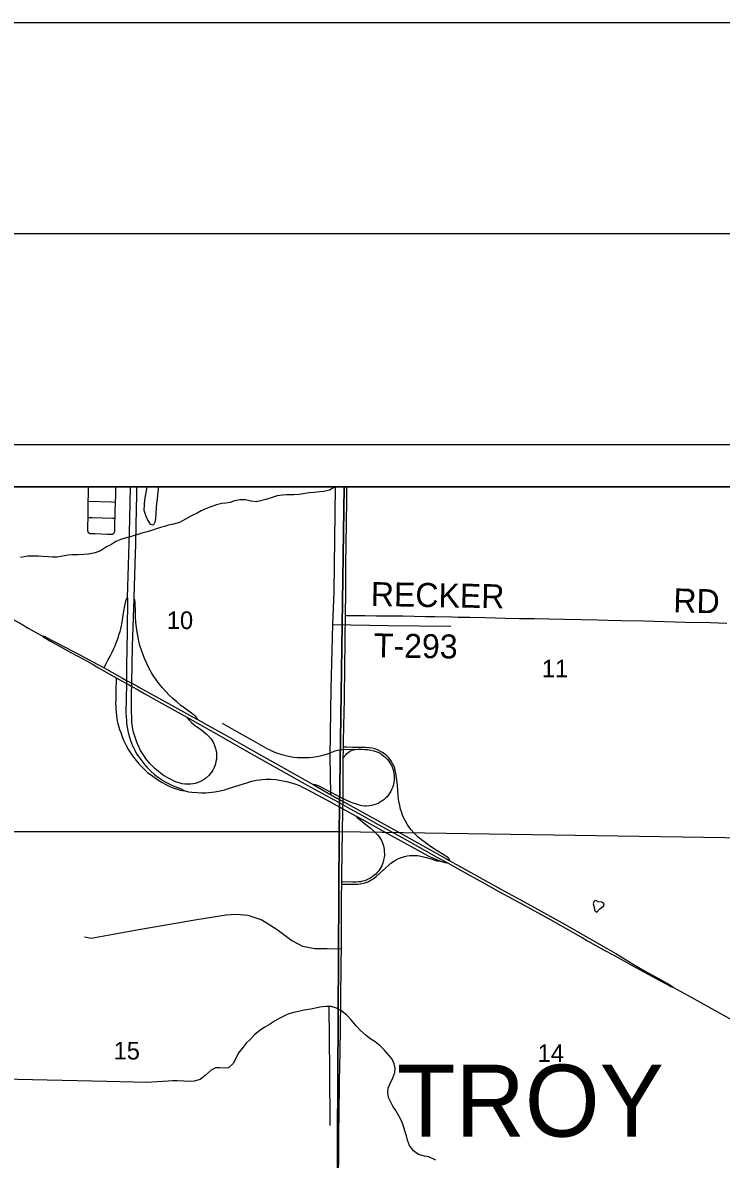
# Model space of a CAD drawing. Extents: x 0 to 34, y 0 to 22.
# Drawn here: x 4.765 to 6.42, y 19.306 to 22 of the extents above; entities that cross this region are included whole.
import ezdxf

# ---------------------------------------------------------------- set-up
doc = ezdxf.new("R2010")
doc.units = 0
for name, color, linetype in [('GM_X_City_Street', 7, 'Continuous'), ('GM_X_County_Road', 7, 'Continuous'), ('GM_X_Interchange_Ramps', 7, 'Continuous'), ('GM_X_Minor_Lake', 7, 'Continuous'), ('GM_X_Minor_River', 7, 'Continuous'), ('GM_X_Section', 7, 'Continuous'), ('GM_X_Section_Text', 7, 'Continuous'), ('GM_X_State_Route', 7, 'Continuous'), ('GM_X_Township_Road', 7, 'Continuous'), ('GM_X_Township_Road_Text', 7, 'Continuous'), ('GM_X_Township_Text', 7, 'Continuous'), ('GM_X_US_Route', 7, 'Continuous'), ('SH_Border', 7, 'Continuous'), ('SH_Cut_Line', 7, 'Continuous'), ('SH_Data', 7, 'Continuous')]:
    doc.layers.add(name, color=color, linetype=linetype)

msp = doc.modelspace()

# ---------------------------------------------------------------- linework, layer by layer
at = {"layer": 'GM_X_City_Street'}
for points in [[(5.527, 20.9), (4.528, 20.9), (4.5187, 20.0828), (5.5144, 20.0832)], [(6.5392, 20.9), (5.527, 20.9), (5.5144, 20.0832), (6.5307, 20.0674)]]:
    msp.add_lwpolyline(points, close=True, dxfattribs=at)
at = {"layer": 'GM_X_County_Road'}
for p, q in [((5.5246, 20.2575), (5.525, 20.2775)), ((5.525, 20.2775), (5.5251, 20.283)), ((5.5209, 19.9584), (5.521, 19.9635))]:
    msp.add_line(p, q, dxfattribs=at)
for points in [[(5.53, 20.5953), (5.5301, 20.6052), (5.5309, 20.6408), (5.5307, 20.6432), (5.5306, 20.6463), (5.5306, 20.6699), (5.5307, 20.681), (5.5308, 20.7165), (5.532, 20.8122), (5.5328, 20.8707), (5.533, 20.9)], [(5.5282, 20.4449), (5.5286, 20.4642), (5.5294, 20.5406), (5.53, 20.5953)], [(5.5251, 20.283), (5.5252, 20.3001), (5.5258, 20.3287), (5.5266, 20.3697), (5.5271, 20.392), (5.5278, 20.4287), (5.5282, 20.4449)], [(5.5238, 20.1423), (5.5239, 20.1461), (5.5241, 20.1541), (5.5241, 20.1556), (5.5242, 20.1605), (5.5243, 20.1661), (5.5244, 20.1909), (5.5245, 20.2504), (5.5246, 20.2575)], [(5.521, 19.9635), (5.5212, 19.9805), (5.522, 20.0334), (5.523, 20.0857), (5.5235, 20.1286), (5.5237, 20.1365), (5.5238, 20.1423)], [(5.5127, 19.2322), (5.5137, 19.3106), (5.5139, 19.3298), (5.5141, 19.3564), (5.5151, 19.4267), (5.5151, 19.4385), (5.5155, 19.4614), (5.5159, 19.4869), (5.5167, 19.5286), (5.517, 19.5572), (5.5177, 19.62), (5.5185, 19.6784), (5.5195, 19.7723), (5.52, 19.8022), (5.52, 19.8158), (5.5203, 19.8643), (5.5201, 19.8942), (5.5204, 19.9271), (5.5209, 19.9584)]]:
    msp.add_lwpolyline(points, dxfattribs=at)
at = {"layer": 'GM_X_Interchange_Ramps'}
for points in [[(5.0127, 20.6371), (5.0125, 20.557), (5.0109, 20.4754), (5.0106, 20.441), (5.0104, 20.434), (5.0098, 20.3976), (5.0095, 20.3658), (5.0096, 20.3549), (5.0104, 20.3453), (5.011, 20.3391), (5.0123, 20.3299), (5.0142, 20.3213), (5.0158, 20.3141), (5.0179, 20.3068), (5.0204, 20.2988), (5.0226, 20.2924), (5.0253, 20.2861), (5.028, 20.2804), (5.0311, 20.2742), (5.0348, 20.2672), (5.0397, 20.2598), (5.0467, 20.25), (5.054, 20.2407), (5.059, 20.2351), (5.0678, 20.2264), (5.0781, 20.2175), (5.0864, 20.211), (5.0938, 20.2058), (5.1007, 20.2016), (5.109, 20.1971), (5.1197, 20.192), (5.1289, 20.1883), (5.1385, 20.1848), (5.1444, 20.182), (5.1493, 20.1791)], [(5.1809, 20.3472), (5.1795, 20.349), (5.178, 20.351), (5.1761, 20.3536), (5.1747, 20.3552), (5.1729, 20.357), (5.1646, 20.3631), (5.1502, 20.3738), (5.1398, 20.3818), (5.1297, 20.39), (5.1203, 20.3982), (5.1118, 20.4064), (5.1036, 20.4149), (5.0958, 20.4238), (5.0883, 20.4329), (5.082, 20.4414), (5.0756, 20.4506), (5.0694, 20.4607), (5.0637, 20.471), (5.0588, 20.4811), (5.0543, 20.4913), (5.0501, 20.5017), (5.0461, 20.5128), (5.0427, 20.5241), (5.0401, 20.5337), (5.038, 20.5434), (5.0359, 20.5551), (5.0343, 20.5662), (5.0331, 20.5779), (5.0323, 20.5928), (5.0319, 20.6095), (5.0315, 20.6189), (5.0311, 20.6282), (5.0305, 20.6312), (5.029, 20.635)], [(4.9865, 20.4469), (4.9856, 20.4121), (4.9852, 20.3968), (4.9849, 20.3867), (4.9851, 20.3802), (4.9855, 20.3734), (4.986, 20.3667), (4.987, 20.3559), (4.9887, 20.3455), (4.9902, 20.3389), (4.9919, 20.3332), (4.9944, 20.3247), (4.9969, 20.3176), (4.9997, 20.3094), (5.0037, 20.2992), (5.0097, 20.2864), (5.0156, 20.2764), (5.0204, 20.2691), (5.0248, 20.2624), (5.0304, 20.2549), (5.0399, 20.2434), (5.0508, 20.232), (5.0606, 20.2231), (5.0728, 20.2138), (5.0851, 20.2053), (5.0955, 20.1991), (5.1038, 20.1945), (5.1154, 20.1889), (5.1233, 20.1856), (5.1314, 20.183), (5.1381, 20.181), (5.1437, 20.18), (5.1493, 20.1791)], [(5.525, 20.2775), (5.5512, 20.2777), (5.5525, 20.2772), (5.5534, 20.2774), (5.5596, 20.2778), (5.5677, 20.2777), (5.5758, 20.2774), (5.5833, 20.2769), (5.59, 20.276), (5.5967, 20.2744), (5.602, 20.2727), (5.6066, 20.2707), (5.6116, 20.2682), (5.6163, 20.2652), (5.6207, 20.2618), (5.6249, 20.2581), (5.6288, 20.2541), (5.6324, 20.2497), (5.6352, 20.2457), (5.638, 20.2408), (5.6402, 20.2363), (5.6421, 20.2311), (5.6435, 20.2263), (5.6446, 20.2208), (5.6453, 20.2153), (5.6455, 20.2103), (5.6453, 20.2047), (5.6447, 20.1998), (5.6436, 20.1943), (5.642, 20.1889), (5.64, 20.1837), (5.6376, 20.1786), (5.6351, 20.1743), (5.6319, 20.1697), (5.6284, 20.1654), (5.6249, 20.1618), (5.6207, 20.1581), (5.6167, 20.1552), (5.612, 20.1522), (5.607, 20.1496), (5.6024, 20.1477), (5.5971, 20.1459), (5.5917, 20.1446), (5.5861, 20.1437), (5.5799, 20.1432), (5.5756, 20.1433), (5.5688, 20.1439), (5.5657, 20.1445), (5.5579, 20.1465), (5.5453, 20.151), (5.5366, 20.1547), (5.5242, 20.1605), (5.4687, 20.1897), (5.4632, 20.1921), (5.4589, 20.1932), (5.4533, 20.1939)], [(5.5246, 20.2575), (5.5308, 20.2646), (5.5333, 20.2674), (5.536, 20.2699), (5.539, 20.2722), (5.5422, 20.2741), (5.5462, 20.2758), (5.5504, 20.2769), (5.5525, 20.2772)], [(5.7772, 20.0136), (5.7762, 20.0159), (5.7754, 20.018), (5.7741, 20.02), (5.7721, 20.0218), (5.7703, 20.023), (5.755, 20.0321), (5.7408, 20.0411), (5.7279, 20.0498), (5.7183, 20.0567), (5.7098, 20.063), (5.7022, 20.0694), (5.6958, 20.0754), (5.6915, 20.0798), (5.6854, 20.0869), (5.6805, 20.0934), (5.676, 20.1001), (5.6719, 20.107), (5.6683, 20.1142), (5.665, 20.1217), (5.6623, 20.1293), (5.6603, 20.1358), (5.6582, 20.1443), (5.6564, 20.1547), (5.6549, 20.1676), (5.6528, 20.1924), (5.6509, 20.2098), (5.6492, 20.2215), (5.6479, 20.2275), (5.6464, 20.2329), (5.6437, 20.2399), (5.6414, 20.2443), (5.6386, 20.2491), (5.6353, 20.2537), (5.6317, 20.258), (5.6278, 20.262), (5.6236, 20.2657), (5.6191, 20.269), (5.6144, 20.272), (5.6089, 20.275), (5.6038, 20.2771), (5.599, 20.2787), (5.593, 20.2802), (5.5856, 20.2814), (5.5763, 20.2819), (5.5465, 20.2823), (5.5328, 20.2828), (5.5251, 20.283)], [(5.1493, 20.1791), (5.1577, 20.1772), (5.1659, 20.1762), (5.1782, 20.175), (5.1878, 20.1746), (5.1989, 20.1748), (5.2061, 20.1753), (5.2203, 20.177), (5.2331, 20.1793), (5.2433, 20.182), (5.2617, 20.1876), (5.2752, 20.1919), (5.2877, 20.1962), (5.298, 20.1993), (5.3081, 20.202), (5.3183, 20.2042), (5.327, 20.2055), (5.3334, 20.2061), (5.3418, 20.2066), (5.3529, 20.2066), (5.3648, 20.2058), (5.3774, 20.2039), (5.3899, 20.2015), (5.3983, 20.1994), (5.4045, 20.1975), (5.4122, 20.1949), (5.4207, 20.1916), (5.4282, 20.1882), (5.439, 20.1827), (5.4951, 20.152), (5.5237, 20.1365), (5.5548, 20.1195)], [(5.5548, 20.1195), (5.5577, 20.116), (5.5605, 20.1134), (5.5642, 20.1103), (5.5752, 20.1019), (5.5879, 20.0916), (5.5959, 20.0845), (5.6014, 20.0792), (5.6054, 20.0751), (5.6095, 20.0699), (5.6124, 20.0656), (5.615, 20.0612), (5.6165, 20.0576), (5.618, 20.0536), (5.6195, 20.0488), (5.6205, 20.0446), (5.6212, 20.0399), (5.6217, 20.034), (5.622, 20.0307), (5.622, 20.0263), (5.6216, 20.022), (5.621, 20.0185), (5.6201, 20.0144), (5.6191, 20.0108), (5.6177, 20.0066), (5.6157, 20.0016), (5.6135, 19.9975), (5.6111, 19.9934), (5.6095, 19.991), (5.607, 19.9877), (5.6042, 19.9848), (5.6016, 19.9821), (5.5964, 19.9776), (5.5926, 19.9748), (5.5876, 19.9716), (5.5836, 19.9695), (5.5789, 19.9675), (5.5753, 19.9662), (5.5709, 19.965), (5.568, 19.9644), (5.5652, 19.9639), (5.5608, 19.9634), (5.5539, 19.9631), (5.5474, 19.9631), (5.5228, 19.9635), (5.521, 19.9635)], [(5.5548, 20.1195), (5.5611, 20.1161), (5.6367, 20.0742), (5.7261, 20.0253), (5.7393, 20.019), (5.7498, 20.0146), (5.7528, 20.0135), (5.757, 20.0119), (5.7659, 20.0091), (5.7729, 20.0074)], [(5.5209, 19.9584), (5.5225, 19.9584), (5.5326, 19.9582), (5.5388, 19.9582), (5.5546, 19.9581), (5.5593, 19.9583), (5.5647, 19.9588), (5.5687, 19.9594), (5.5727, 19.9603), (5.5766, 19.9615), (5.5808, 19.9629), (5.584, 19.9643), (5.5884, 19.9664), (5.593, 19.9692), (5.5981, 19.9726), (5.6028, 19.9765), (5.6254, 19.9969), (5.6326, 20.0034), (5.6376, 20.0078), (5.6435, 20.012), (5.6481, 20.015), (5.6537, 20.0179), (5.6604, 20.0206), (5.6695, 20.0234), (5.6758, 20.0248), (5.6825, 20.0257), (5.6877, 20.0261), (5.6938, 20.0262), (5.7011, 20.0257), (5.7081, 20.0245), (5.7145, 20.0231), (5.7208, 20.0214), (5.7325, 20.0177), (5.7419, 20.0148), (5.7463, 20.0137), (5.7498, 20.0132), (5.7528, 20.0135)]]:
    msp.add_lwpolyline(points, dxfattribs=at)
at = {"layer": 'GM_X_Minor_Lake'}
msp.add_line((6.1321, 19.8986), (6.1357, 19.9021), dxfattribs=at)
for points in [[(5.0588, 20.9), (5.0579, 20.8952), (5.0531, 20.8688), (5.0521, 20.8449), (5.0567, 20.8304), (5.0614, 20.8204), (5.0672, 20.8115), (5.0728, 20.8095), (5.0759, 20.8109), (5.0791, 20.8184), (5.0807, 20.8351), (5.0822, 20.8521), (5.0839, 20.8726), (5.0863, 20.8949), (5.0864, 20.9)], [(6.1357, 19.9021), (6.1414, 19.9062), (6.1431, 19.9114), (6.1375, 19.915), (6.1288, 19.9163), (6.1228, 19.9191), (6.1194, 19.9181), (6.1166, 19.9113), (6.119, 19.9029), (6.1211, 19.8949), (6.1259, 19.8914), (6.1321, 19.8986)]]:
    msp.add_lwpolyline(points, dxfattribs=at)
at = {"layer": 'GM_X_Minor_River'}
for points in [[(5.5053, 20.9), (5.5053, 20.9), (5.4918, 20.8923), (5.4781, 20.8892), (5.4686, 20.888), (5.4553, 20.8868), (5.444, 20.8855), (5.4341, 20.8839), (5.42, 20.8819), (5.4075, 20.8807), (5.3908, 20.8807), (5.3806, 20.8802), (5.368, 20.8782), (5.3558, 20.8744), (5.3409, 20.8702), (5.3314, 20.8674), (5.3188, 20.8646), (5.3052, 20.8661), (5.2928, 20.8691), (5.2792, 20.8694), (5.267, 20.8663), (5.2567, 20.8631), (5.2464, 20.8615), (5.2369, 20.8602), (5.2244, 20.8574), (5.2106, 20.8528), (5.2003, 20.8489), (5.188, 20.8428), (5.178, 20.8373), (5.1631, 20.8301), (5.1504, 20.8236), (5.1362, 20.8155), (5.1225, 20.8117), (5.1103, 20.809), (5.1008, 20.8058), (5.0912, 20.8034), (5.0817, 20.8002), (5.0679, 20.7956), (5.0569, 20.7924), (5.047, 20.79), (5.0325, 20.785), (5.0214, 20.7819), (5.01, 20.7788), (4.997, 20.7749), (4.9855, 20.7706), (4.9732, 20.7626), (4.9636, 20.7575), (4.949, 20.7484), (4.9364, 20.7437), (4.9208, 20.7403), (4.9094, 20.7391), (4.8957, 20.739), (4.8829, 20.7389), (4.8726, 20.7381), (4.86, 20.7353), (4.846, 20.7334), (4.8357, 20.7329), (4.8255, 20.7339), (4.8119, 20.7346), (4.8017, 20.7352), (4.79, 20.7355), (4.7771, 20.7354), (4.7592, 20.7324)], [(5.5053, 20.9), (5.5018, 20.6511), (5.4991, 20.5734), (5.4953, 20.4213), (5.4928, 20.2608), (5.494, 20.1716)], [(5.4991, 20.5734), (5.63, 20.5713), (5.7792, 20.5692)], [(5.1098, 19.4913), (5.0582, 19.488), (4.9639, 19.4903), (4.8584, 19.4928), (4.7527, 19.4946), (4.7304, 19.4963), (4.7225, 19.4984), (4.7147, 19.5046), (4.7116, 19.5142), (4.6997, 19.5847), (4.6742, 19.733), (4.6549, 19.8537), (4.6284, 20.0077), (4.6, 20.1602), (4.5827, 20.2563)], [(5.744, 19.304), (5.7275, 19.3116), (5.717, 19.313), (5.703, 19.3172), (5.6908, 19.3262), (5.6812, 19.3386), (5.677, 19.3512), (5.6746, 19.3615), (5.6714, 19.371), (5.6679, 19.381), (5.6633, 19.3952), (5.6561, 19.4086), (5.6488, 19.4213), (5.6423, 19.4321), (5.6365, 19.4425), (5.6314, 19.4521), (5.6302, 19.4646), (5.6312, 19.4745), (5.636, 19.4858), (5.6421, 19.4993), (5.6465, 19.5113), (5.6475, 19.5215), (5.6455, 19.5318), (5.6405, 19.543), (5.6328, 19.5526), (5.6213, 19.5654), (5.6117, 19.5748), (5.6002, 19.5845), (5.5898, 19.5905), (5.5786, 19.5991), (5.5657, 19.6112), (5.555, 19.6221), (5.5436, 19.6364), (5.5318, 19.6484), (5.5188, 19.6582), (5.5087, 19.6638), (5.4959, 19.6679), (5.4838, 19.6678), (5.4686, 19.6663), (5.4587, 19.6639), (5.4476, 19.6619), (5.4317, 19.6592), (5.4184, 19.6565), (5.4073, 19.6541)], [(5.4905, 19.6679), (5.4921, 19.5158), (5.493, 19.3856)], [(5.4073, 19.6541), (5.3955, 19.6506), (5.3855, 19.6459), (5.3744, 19.6401), (5.3614, 19.6336), (5.3494, 19.6255), (5.3383, 19.619), (5.3275, 19.6116), (5.3147, 19.6017), (5.305, 19.5902), (5.2945, 19.5813), (5.2875, 19.5716), (5.2769, 19.559), (5.2706, 19.547), (5.2646, 19.5338), (5.2526, 19.5224), (5.2423, 19.5219), (5.2314, 19.5225), (5.2215, 19.5224), (5.2112, 19.5173), (5.1968, 19.5047), (5.1856, 19.4951), (5.1713, 19.4911), (5.1571, 19.4901), (5.1465, 19.4912), (5.131, 19.4919), (5.1204, 19.4918), (5.1098, 19.4913)]]:
    msp.add_lwpolyline(points, dxfattribs=at)
at = {"layer": 'GM_X_Section'}
for points in [[(5.5144, 20.0832), (5.5091, 19.0615), (4.5106, 19.0706), (4.5187, 20.0828)], [(6.5307, 20.0674), (6.5168, 19.0579), (5.5091, 19.0615), (5.5144, 20.0832)]]:
    msp.add_lwpolyline(points, close=True, dxfattribs=at)
at = {"layer": 'GM_X_State_Route'}
msp.add_line((5.032, 20.7425), (5.0325, 20.7625), dxfattribs=at)
for points in [[(4.9574, 20.4707), (4.9621, 20.4798), (4.9667, 20.4886), (4.9728, 20.4999), (4.977, 20.5079), (4.981, 20.5164), (4.9839, 20.5232), (4.9866, 20.5304), (4.9914, 20.544), (4.9937, 20.5511), (4.9954, 20.5569), (4.9971, 20.5635), (4.9987, 20.5704), (5.0016, 20.5846), (5.0046, 20.6054), (5.0067, 20.6181), (5.0082, 20.6246), (5.0094, 20.6294), (5.0109, 20.6333), (5.0127, 20.6371), (5.0179, 20.7919), (5.0187, 20.824), (5.0203, 20.9)], [(5.0325, 20.7625), (5.0339, 20.8135), (5.0345, 20.8411), (5.0351, 20.8866), (5.0355, 20.9)], [(5.029, 20.635), (5.0292, 20.6384), (5.032, 20.7425)], [(5.1538, 20.3535), (5.1593, 20.3466), (5.1651, 20.3409), (5.1751, 20.3329), (5.1858, 20.3251), (5.189, 20.3228), (5.1993, 20.3146), (5.2066, 20.3075), (5.2099, 20.3038), (5.2129, 20.2997), (5.2166, 20.2932), (5.2193, 20.287), (5.2218, 20.2799), (5.2228, 20.2767), (5.2237, 20.2713), (5.2243, 20.2653), (5.2242, 20.2598), (5.2239, 20.2546), (5.2228, 20.2491), (5.2214, 20.2433), (5.2198, 20.2385), (5.2175, 20.2327), (5.2153, 20.2284), (5.2123, 20.2236), (5.2055, 20.2157), (5.1977, 20.2086), (5.1935, 20.2055), (5.1875, 20.2021), (5.1804, 20.1989), (5.1737, 20.1967), (5.1687, 20.1957), (5.163, 20.195), (5.1555, 20.1949), (5.1489, 20.1953), (5.1427, 20.1962), (5.1357, 20.1982), (5.1295, 20.2001), (5.1225, 20.2031), (5.1164, 20.206), (5.1102, 20.2091), (5.0988, 20.2158), (5.0867, 20.2247), (5.0782, 20.2319), (5.0714, 20.2382), (5.0658, 20.2441), (5.0585, 20.2534), (5.0516, 20.2631), (5.0442, 20.275), (5.0382, 20.2873), (5.0352, 20.2944), (5.0312, 20.3063), (5.0282, 20.316), (5.0261, 20.3237), (5.0246, 20.3328), (5.0235, 20.3408), (5.0231, 20.3509), (5.0226, 20.3693), (5.0229, 20.415), (5.0231, 20.4269), (5.0232, 20.4342), (5.0249, 20.5221), (5.029, 20.635)]]:
    msp.add_lwpolyline(points, dxfattribs=at)
at = {"layer": 'GM_X_Township_Road'}
for points in [[(4.9198, 20.9), (4.9195, 20.8817), (4.9191, 20.8657)], [(4.9847, 20.8639), (4.9851, 20.8782), (4.9858, 20.9)], [(4.9191, 20.8657), (4.919, 20.8397), (4.9188, 20.8274)], [(4.9191, 20.8657), (4.9752, 20.8642), (4.9847, 20.8639)], [(4.9835, 20.8256), (4.9837, 20.8303), (4.9841, 20.8415), (4.9847, 20.8639)], [(4.9188, 20.8274), (4.9185, 20.8064), (4.9185, 20.7966), (4.9186, 20.7957), (4.9188, 20.7946), (4.9191, 20.7938), (4.9194, 20.7931), (4.9197, 20.7925), (4.9202, 20.7918), (4.9208, 20.7912), (4.9215, 20.7907), (4.9221, 20.7902), (4.9227, 20.7898), (4.9235, 20.7896), (4.9243, 20.7893), (4.9253, 20.7891), (4.9283, 20.7889), (4.9363, 20.7889), (4.9653, 20.7877), (4.9757, 20.7873), (4.9765, 20.7873), (4.9773, 20.7875), (4.978, 20.7879), (4.9786, 20.7882), (4.9793, 20.7887), (4.9799, 20.7892), (4.9805, 20.7898), (4.981, 20.7903), (4.9816, 20.7912), (4.9822, 20.7924), (4.9825, 20.793), (4.9828, 20.7938), (4.9829, 20.7946), (4.9834, 20.8204), (4.9835, 20.8256)], [(4.9188, 20.8274), (4.9301, 20.8271), (4.9773, 20.8258), (4.9835, 20.8256)], [(5.53, 20.5953), (5.5318, 20.5952), (5.5449, 20.595), (5.5759, 20.5947), (5.6033, 20.5943), (5.6655, 20.5938), (5.7202, 20.5928), (5.7413, 20.5926), (5.7827, 20.5917), (5.7969, 20.5913), (5.8244, 20.5907), (5.8604, 20.59), (5.9092, 20.5887), (5.9415, 20.5879), (5.9776, 20.5876), (6.0118, 20.5869), (6.0484, 20.586), (6.0882, 20.5853), (6.1268, 20.5844), (6.1516, 20.5838), (6.1833, 20.583), (6.2368, 20.5821), (6.3356, 20.5794), (6.3942, 20.5779), (6.434, 20.5768)], [(5.2372, 20.3395), (5.2653, 20.3235), (5.312, 20.2976), (5.3451, 20.2791), (5.3523, 20.2754), (5.3597, 20.272), (5.3685, 20.2687), (5.3786, 20.2654), (5.3882, 20.2628), (5.398, 20.2607), (5.4072, 20.2592), (5.4159, 20.2583), (5.4259, 20.2579), (5.4353, 20.2579), (5.444, 20.2583), (5.4527, 20.2592), (5.4613, 20.2606), (5.4699, 20.2623), (5.4789, 20.2647), (5.4897, 20.2679), (5.5056, 20.2737), (5.511, 20.2754), (5.5144, 20.2762), (5.5179, 20.2768), (5.525, 20.2775)], [(4.9109, 19.8331), (4.9272, 19.83), (5.0398, 19.8507), (5.1771, 19.8745), (5.2471, 19.8851), (5.2709, 19.8868), (5.2981, 19.8842), (5.3312, 19.8736), (5.3681, 19.8507), (5.4024, 19.8243), (5.428, 19.8107), (5.457, 19.8054), (5.4865, 19.8054), (5.52, 19.8046)]]:
    msp.add_lwpolyline(points, dxfattribs=at)
at = {"layer": 'GM_X_US_Route'}
for p, q in [((4.7847, 20.5612), (4.8092, 20.5478)), ((4.9512, 20.4671), (4.9865, 20.4469)), ((6.0861, 19.8337), (6.0905, 19.8313))]:
    msp.add_line(p, q, dxfattribs=at)
for points in [[(7.5667, 20.9), (2.1, 20.9)], [(4.7404, 20.5864), (4.7608, 20.5749), (4.7795, 20.5641), (4.7847, 20.5612)], [(4.8092, 20.5478), (4.8108, 20.5463), (4.8127, 20.5448), (4.8145, 20.5435), (4.817, 20.5418), (4.82, 20.54), (4.829, 20.535), (4.8591, 20.5183), (4.8775, 20.5081), (4.8966, 20.4978), (4.9178, 20.4865), (4.93, 20.4798), (4.933, 20.478), (4.9365, 20.4759), (4.9443, 20.4711), (4.9512, 20.4671)], [(4.8092, 20.5478), (4.8124, 20.5469), (4.815, 20.5459), (4.8176, 20.5447), (4.8194, 20.5437), (4.8393, 20.5331), (4.8605, 20.5222), (4.8853, 20.5096), (4.9118, 20.4957), (4.9313, 20.485), (4.9574, 20.4707), (4.9633, 20.4674), (5.0015, 20.446), (5.0106, 20.441), (5.0232, 20.4342), (5.0365, 20.427), (5.0399, 20.4251)], [(4.9865, 20.4469), (5.0104, 20.434), (5.0143, 20.4319), (5.0231, 20.4269), (5.0278, 20.4243)], [(5.0278, 20.4243), (5.0334, 20.4212), (5.0368, 20.4193)], [(5.0399, 20.4251), (5.0805, 20.4026), (5.1244, 20.3783), (5.1675, 20.3546), (5.1809, 20.3472), (5.2045, 20.3342), (5.2443, 20.312), (5.2834, 20.2901), (5.3308, 20.2631), (5.3848, 20.2327), (5.4332, 20.2052), (5.4533, 20.1939), (5.5096, 20.1621), (5.5241, 20.1541), (5.5788, 20.1236), (5.6728, 20.0716), (5.7533, 20.0269), (5.7772, 20.0136), (5.8414, 19.9779), (5.9069, 19.9416), (5.9703, 19.9068), (6.0505, 19.8622), (6.1251, 19.8201), (6.1485, 19.8064), (6.1705, 19.7933), (6.2118, 19.7684), (6.2388, 19.7527), (6.2649, 19.738), (6.3, 19.7183), (6.302, 19.7171), (6.3036, 19.7161), (6.3055, 19.7147), (6.3074, 19.7131)], [(5.0368, 20.4193), (5.054, 20.4095), (5.0881, 20.3902), (5.1326, 20.3656), (5.1538, 20.3535)], [(5.1538, 20.3535), (5.2349, 20.3079), (5.3108, 20.2649), (5.3126, 20.2639)], [(5.3126, 20.2639), (5.3506, 20.2426), (5.3956, 20.2173), (5.4392, 20.1928), (5.4825, 20.1692), (5.5129, 20.1522), (5.5239, 20.1461), (5.541, 20.1367), (5.5612, 20.1254), (5.6071, 20.0998), (5.6641, 20.0684), (5.7466, 20.0222), (5.7729, 20.0074)], [(5.7729, 20.0074), (5.8024, 19.9912), (5.8565, 19.9615), (5.8935, 19.941), (5.9529, 19.9084), (6.0163, 19.8731), (6.0861, 19.8337)], [(6.0905, 19.8313), (6.1036, 19.8239), (6.1429, 19.8019)], [(6.1429, 19.8019), (6.1639, 19.7902), (6.2092, 19.7649), (6.2732, 19.7303), (6.2986, 19.7167), (6.301, 19.7154), (6.303, 19.7146), (6.3049, 19.7139), (6.3074, 19.7131)], [(6.3074, 19.7131), (6.3421, 19.6939), (6.4402, 19.6394), (6.4611, 19.6277), (6.4904, 19.6113), (6.5273, 19.5908)]]:
    msp.add_lwpolyline(points, dxfattribs=at)
at = {"layer": 'SH_Border'}
msp.add_lwpolyline([(1.5, 21.5), (33.5, 21.5), (33.5, 0.5), (1.5, 0.5)], close=True, dxfattribs=at)
at = {"layer": 'SH_Cut_Line'}
msp.add_lwpolyline([(0, 0), (34, 0), (34, 22), (0, 22)], close=True, dxfattribs=at)
msp.add_lwpolyline([(7.5667, 20.9), (2.1, 20.9), (2.1, 14.1)], dxfattribs=at)
at = {"layer": 'SH_Data'}
for p, q in [((2, 21), (9, 21)), ((2.1, 20.9), (8.9, 20.9))]:
    msp.add_line(p, q, dxfattribs=at)

# ---------------------------------------------------------------- texts
at = {"layer": 'GM_X_Section_Text'}
for s, p in [('10', (5.1064, 20.5627)), ('11', (5.9952, 20.4481)), ('15', (4.9802, 19.5424)), ('14', (5.9852, 19.5363))]:
    msp.add_text(s, height=0.04186, rotation=0, dxfattribs=at).set_placement(p)
at = {"layer": 'GM_X_Township_Road_Text'}
for s, rotation, p in [('RECKER', 358.958, (5.5894, 20.6175)), ('RD', 358.5235, (6.3063, 20.6025)), ('T-293', 359.1669, (5.5967, 20.4957))]:
    msp.add_text(s, height=0.05682, rotation=rotation, dxfattribs=at).set_placement(p)
at = {"layer": 'GM_X_Township_Text'}
msp.add_text('TROY', height=0.17045, rotation=0, dxfattribs=at).set_placement((5.6511, 19.3596))

doc.saveas('drawing.dxf')
